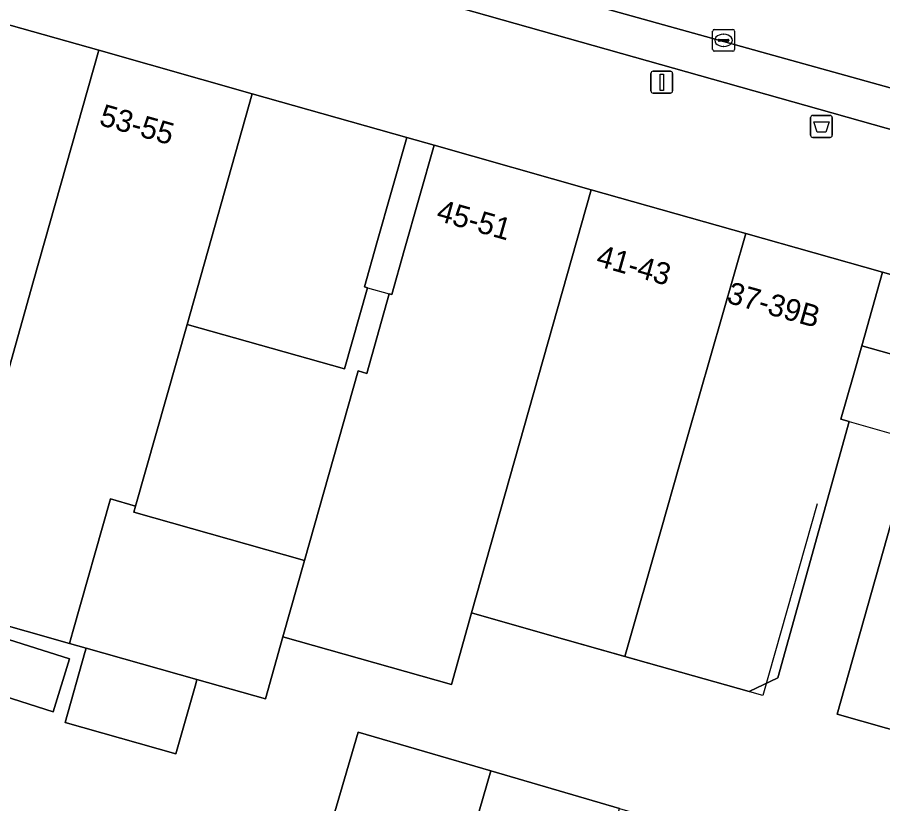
# Model space of a CAD drawing. Extents: x 158086 to 159499, y 382904 to 383981.
# Drawn here: x 158796.14 to 158835.7, y 383257.98 to 383293.91 of the extents above; entities that cross this region are included whole.
import ezdxf

# ---------------------------------------------------------------- set-up
doc = ezdxf.new("R2010")
doc.units = 0
for name, color, linetype in [('IMGEO_Afvalbak', 7, 'Continuous'), ('IMGEO_Erf', 7, 'Continuous'), ('IMGEO_Kolk', 7, 'Continuous'), ('IMGEO_Lichtmast', 7, 'Continuous'), ('IMGEO_Muur', 7, 'Continuous'), ('IMGEO_Pand', 7, 'Continuous'), ('IMGEO_Pand_nummerreeks', 7, 'Continuous'), ('IMGEO_Pand_overbouw', 7, 'Continuous'), ('IMGEO_Parkeervlak_open', 7, 'Continuous'), ('IMGEO_Rijbaan_lokaal_gesloten', 7, 'Continuous'), ('IMGEO_Voetpad_open', 7, 'Continuous')]:
    doc.layers.add(name, color=color, linetype=linetype)

msp = doc.modelspace()

# ---------------------------------------------------------------- linework, layer by layer
at = {"layer": 'IMGEO_Afvalbak'}
for p, q in [((158832.411, 383288.526), (158832.411, 383289.326)), ((158832.411, 383289.326), (158832.411, 383288.526)), ((158832.511, 383289.426), (158833.301, 383289.426)), ((158833.301, 383289.426), (158832.511, 383289.426)), ((158833.401, 383289.326), (158833.401, 383288.526)), ((158833.401, 383288.526), (158833.401, 383289.326)), ((158833.301, 383288.426), (158832.511, 383288.426)), ((158832.511, 383288.426), (158833.301, 383288.426))]:
    msp.add_line(p, q, dxfattribs=at)
msp.add_lwpolyline([(158832.554, 383289.14), (158833.258, 383289.14), (158833.109, 383288.67), (158832.703, 383288.67), (158832.554, 383289.14)], dxfattribs=at)
for centre, start, end in [((158832.511, 383289.326), 90, 180), ((158832.511, 383289.326), 90, 180), ((158833.301, 383289.326), 0, 90), ((158833.301, 383289.326), 360, 90), ((158832.511, 383288.526), 180, 270), ((158832.511, 383288.526), 180, 270), ((158833.301, 383288.526), 270, 0), ((158833.301, 383288.526), 270, 0)]:
    msp.add_arc(centre, 0.1, start, end, dxfattribs=at)
at = {"layer": 'IMGEO_Erf'}
for points in [[(158811.719, 383277.751), (158812.119, 383277.638), (158813.147, 383281.273), (158813.26, 383281.241), (158813.83, 383283.255), (158815.192, 383288.065), (158813.942, 383288.419), (158812.58, 383283.609), (158812.01, 383281.595), (158812.145, 383281.557), (158811.095, 383277.845), (158803.902, 383279.88), (158801.552, 383271.575), (158801.472, 383271.292), (158809.271, 383269.086)], [(158797.775, 383262.18), (158794.048, 383263.355), (158794.807, 383265.763), (158798.534, 383264.589)], [(158827.728, 383250.583), (158822.063, 383252.236), (158816.186, 383253.951), (158810.112, 383255.724), (158811.724, 383261.246), (158817.797, 383259.473), (158823.675, 383257.758), (158829.339, 383256.105), (158835.286, 383254.37), (158841.275, 383252.623), (158839.356, 383246.045), (158833.367, 383247.792), (158833.498, 383248.242), (158827.551, 383249.977)]]:
    msp.add_lwpolyline(points, close=True, dxfattribs=at)
for points in [[(158839.065, 383281.31), (158835.697, 383282.263), (158834.747, 383278.905), (158834.336, 383277.452), (158833.796, 383275.547), (158834.175, 383275.44), (158830.905, 383263.724), (158829.595, 383263.099), (158823.912, 383264.707), (158820.362, 383265.712), (158816.906, 383266.69), (158815.984, 383263.429), (158808.286, 383265.603), (158807.483, 383262.767), (158804.352, 383263.652), (158804.299, 383263.46), (158803.396, 383260.256), (158798.326, 383261.684), (158799.228, 383264.888), (158799.283, 383265.084), (158798.527, 383265.297), (158792.672, 383266.951)], [(158840.492, 383260.121), (158833.621, 383262.065), (158837.133, 383274.48)]]:
    msp.add_lwpolyline(points, dxfattribs=at)
at = {"layer": 'IMGEO_Kolk'}
for p, q in [((158827.931, 383292.434), (158827.931, 383293.286)), ((158828.006, 383293.36), (158828.858, 383293.36)), ((158828.932, 383293.286), (158828.932, 383292.434)), ((158828.19, 383292.854), (158828.19, 383292.866)), ((158828.628, 383292.817), (158828.23, 383292.817)), ((158828.233, 383292.903), (158828.631, 383292.903)), ((158828.419, 383293.14), (158828.444, 383293.14)), ((158828.674, 383292.866), (158828.674, 383292.854)), ((158828.442, 383292.58), (158828.417, 383292.58)), ((158828.858, 383292.36), (158828.006, 383292.36))]:
    msp.add_line(p, q, dxfattribs=at)
for points in [[(158827.931, 383292.434), (158827.931, 383293.286)], [(158828.006, 383293.36), (158828.858, 383293.36)], [(158828.932, 383293.286), (158828.932, 383292.434)], [(158828.858, 383292.36), (158828.006, 383292.36)]]:
    msp.add_lwpolyline(points, dxfattribs=at)
for centre, radius, start, end in [((158828.008, 383293.284), 0.0765, 91.552, 178.448), ((158828.008, 383293.284), 0.0765, 91.552, 178.448), ((158828.856, 383293.284), 0.0765, 1.552, 88.448), ((158828.856, 383293.284), 0.0765, 1.552, 88.448), ((158828.23, 383292.863), 0.0403, 85.8775, 175.7526), ((158828.227, 383292.853), 0.0366, 178.938, 274.7102), ((158828.631, 383292.86), 0.043, 264.8664, 352.4533), ((158828.635, 383292.865), 0.0386, 1.7309, 96.639), ((158828.008, 383292.436), 0.0765, 181.552, 268.448), ((158828.008, 383292.436), 0.0765, 181.552, 268.448), ((158828.856, 383292.436), 0.0765, 271.552, 358.448), ((158828.856, 383292.436), 0.0765, 271.552, 358.448)]:
    msp.add_arc(centre, radius, start, end, dxfattribs=at)
for centre, major_axis, ratio, start_param, end_param in [((158828.418, 383292.86), (-0.387, 0.002), 0.722429, 4.712389, 7.853982), ((158828.443, 383292.86), (-0.39, 0.002), 0.717154, 1.570796, 4.712389)]:
    msp.add_ellipse(centre, major_axis=major_axis, ratio=ratio, start_param=start_param, end_param=end_param, dxfattribs=at)
at = {"layer": 'IMGEO_Lichtmast'}
for p, q in [((158825.109, 383290.546), (158825.109, 383291.346)), ((158825.109, 383291.346), (158825.109, 383290.546)), ((158825.209, 383291.446), (158825.999, 383291.446)), ((158825.999, 383291.446), (158825.209, 383291.446)), ((158826.099, 383291.346), (158826.099, 383290.546)), ((158826.099, 383290.546), (158826.099, 383291.346)), ((158825.999, 383290.446), (158825.209, 383290.446)), ((158825.209, 383290.446), (158825.999, 383290.446))]:
    msp.add_line(p, q, dxfattribs=at)
msp.add_lwpolyline([(158825.529, 383291.321), (158825.679, 383291.321), (158825.679, 383290.571), (158825.529, 383290.571), (158825.529, 383291.321)], dxfattribs=at)
for centre, start, end in [((158825.209, 383291.346), 90, 180), ((158825.209, 383291.346), 90, 180), ((158825.999, 383291.346), 0, 90), ((158825.999, 383291.346), 360, 90), ((158825.209, 383290.546), 180, 270), ((158825.209, 383290.546), 180, 270), ((158825.999, 383290.546), 270, 0), ((158825.999, 383290.546), 270, 0)]:
    msp.add_arc(centre, 0.1, start, end, dxfattribs=at)
at = {"layer": 'IMGEO_Muur'}
msp.add_lwpolyline([(158832.702, 383271.679), (158830.226, 383262.922), (158820.362, 383265.712)], dxfattribs=at)
at = {"layer": 'IMGEO_Pand'}
for points in [[(158799.862, 383292.403), (158790.372, 383295.088), (158789.01, 383290.277), (158787.39, 383284.552), (158787.014, 383283.22), (158784.076, 383284.05), (158780.209, 383270.504), (158792.672, 383266.951), (158794.423, 383273.149), (158796.885, 383281.865)], [(158806.883, 383290.416), (158799.862, 383292.403), (158796.885, 383281.865), (158794.423, 383273.149), (158792.672, 383266.951), (158798.527, 383265.297), (158798.682, 383265.847), (158800.395, 383271.902), (158801.552, 383271.575), (158803.902, 383279.88)], [(158812.58, 383283.609), (158813.942, 383288.419), (158806.883, 383290.416), (158803.902, 383279.88), (158811.095, 383277.845), (158812.145, 383281.557), (158812.01, 383281.595)], [(158822.379, 383286.031), (158815.192, 383288.065), (158813.83, 383283.255), (158813.26, 383281.241), (158813.147, 383281.273), (158812.119, 383277.638), (158811.719, 383277.751), (158809.271, 383269.086), (158808.286, 383265.603), (158815.984, 383263.429), (158816.906, 383266.69)], [(158829.444, 383284.032), (158822.379, 383286.031), (158816.906, 383266.69), (158820.362, 383265.712), (158823.912, 383264.707), (158825.57, 383270.5), (158826.417, 383273.457), (158826.786, 383274.746)], [(158834.747, 383278.905), (158835.697, 383282.263), (158829.444, 383284.032), (158826.786, 383274.746), (158826.417, 383273.457), (158825.57, 383270.5), (158823.912, 383264.707), (158829.595, 383263.099), (158830.905, 383263.724), (158834.175, 383275.44), (158833.796, 383275.547), (158834.336, 383277.452)], [(158845.937, 383279.365), (158839.065, 383281.31), (158838.115, 383277.952), (158837.94, 383277.332), (158837.704, 383276.499), (158837.165, 383274.593), (158837.133, 383274.48), (158833.621, 383262.065), (158840.492, 383260.121)], [(158801.552, 383271.575), (158800.395, 383271.902), (158798.682, 383265.847), (158798.527, 383265.297), (158799.283, 383265.084), (158804.352, 383263.652), (158807.483, 383262.767), (158808.286, 383265.603), (158809.271, 383269.086), (158801.472, 383271.292)], [(158794.807, 383265.763), (158794.048, 383263.355), (158797.775, 383262.18), (158798.534, 383264.589)], [(158804.352, 383263.652), (158799.283, 383265.084), (158799.228, 383264.888), (158798.326, 383261.684), (158803.396, 383260.256), (158804.299, 383263.46)], [(158817.797, 383259.473), (158811.724, 383261.246), (158810.112, 383255.724), (158816.186, 383253.951)], [(158823.675, 383257.758), (158817.797, 383259.473), (158816.186, 383253.951), (158822.063, 383252.236)]]:
    msp.add_lwpolyline(points, close=True, dxfattribs=at)
at = {"layer": 'IMGEO_Pand_overbouw'}
for points in [[(158813.942, 383288.419), (158812.58, 383283.609), (158812.01, 383281.595), (158812.145, 383281.557), (158813.147, 383281.273), (158813.26, 383281.241), (158813.83, 383283.255), (158815.192, 383288.065)], [(158835.697, 383282.263), (158834.747, 383278.905), (158838.115, 383277.952), (158839.065, 383281.31)], [(158837.94, 383277.332), (158838.115, 383277.952), (158834.747, 383278.905), (158834.336, 383277.452), (158833.796, 383275.547), (158834.175, 383275.44), (158837.165, 383274.593), (158837.704, 383276.499)]]:
    msp.add_lwpolyline(points, close=True, dxfattribs=at)
at = {"layer": 'IMGEO_Parkeervlak_open'}
for points in [[(158882.839, 383277.452), (158856.776, 383284.933), (158803.212, 383299.825)], [(158805.522, 383297.423), (158810.362, 383296.057), (158836.457, 383288.671), (158842.336, 383287.013), (158883.452, 383275.237)]]:
    msp.add_lwpolyline(points, dxfattribs=at)
at = {"layer": 'IMGEO_Rijbaan_lokaal_gesloten'}
msp.add_lwpolyline([(158779.722, 383306.519), (158801.091, 383300.409), (158803.212, 383299.825), (158856.776, 383284.933), (158882.839, 383277.452)], dxfattribs=at)
at = {"layer": 'IMGEO_Voetpad_open'}
for points in [[(158883.452, 383275.237), (158842.336, 383287.013), (158842.039, 383285.838), (158836.095, 383287.571), (158836.457, 383288.671), (158810.362, 383296.057), (158805.522, 383297.423)], [(158790.372, 383295.088), (158799.862, 383292.403), (158806.883, 383290.416), (158813.942, 383288.419), (158815.192, 383288.065), (158822.379, 383286.031), (158829.444, 383284.032), (158835.697, 383282.263), (158839.065, 383281.31), (158845.937, 383279.365), (158852.621, 383277.474), (158859.187, 383275.616), (158865.516, 383273.825), (158866.482, 383276.877), (158903.057, 383266.48)]]:
    msp.add_lwpolyline(points, dxfattribs=at)

# ---------------------------------------------------------------- texts
at = {"layer": 'IMGEO_Pand_nummerreeks'}
for s, rotation, p in [('53-55', 344.1978, (158799.838, 383289.001)), ('45-51', 344.1978, (158815.248, 383284.64)), ('41-43', 344.2036, (158822.552, 383282.573)), ('37-39B', 344.2036, (158828.523, 383280.884))]:
    msp.add_text(s, height=1, rotation=rotation, dxfattribs=at).set_placement(p)

doc.saveas('drawing.dxf')
